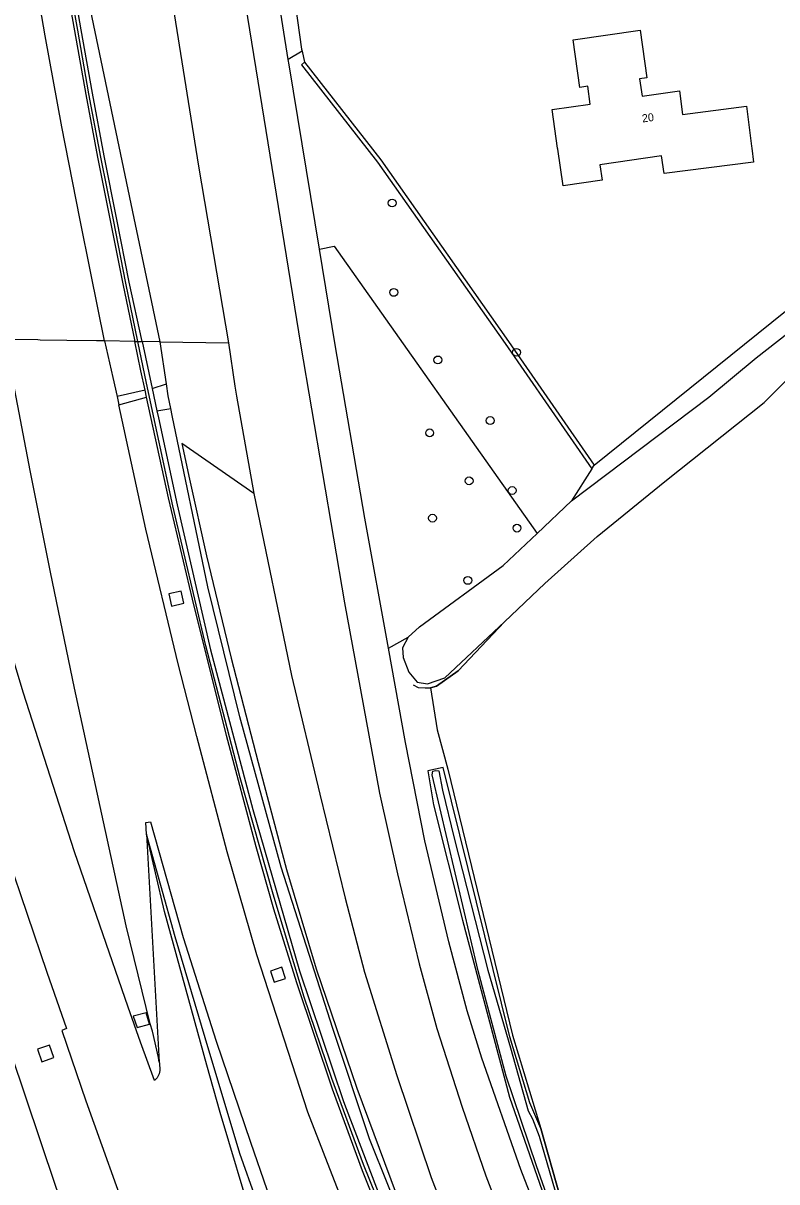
# Model space of a CAD drawing. Extents: x 157663 to 158496, y 379212 to 380934.
# Drawn here: x 158053.2 to 158147.4, y 379870.8 to 380015.6 of the extents above; entities that cross this region are included whole.
import ezdxf

# ---------------------------------------------------------------- set-up
doc = ezdxf.new("R2010")
doc.units = 0
for name, color, linetype in [('IMGEO_Berm_groen', 7, 'Continuous'), ('IMGEO_Boom', 7, 'Continuous'), ('IMGEO_Geluidsscherm', 7, 'Continuous'), ('IMGEO_Grasland_agrarisch', 7, 'Continuous'), ('IMGEO_Grasland_overig', 7, 'Continuous'), ('IMGEO_Groenvoorziening', 7, 'Continuous'), ('IMGEO_Haag', 7, 'Continuous'), ('IMGEO_Loofbos', 7, 'Continuous'), ('IMGEO_Muur', 7, 'Continuous'), ('IMGEO_Pand', 7, 'Continuous'), ('IMGEO_Pand_nummerreeks', 7, 'Continuous'), ('IMGEO_Rijbaan_autosnelweg', 7, 'Continuous'), ('IMGEO_Rijbaan_autoweg', 7, 'Continuous'), ('IMGEO_Rijbaan_lokaal_gesloten', 7, 'Continuous'), ('IMGEO_Voetpad_open', 7, 'Continuous'), ('IMGEO_Waterloop', 7, 'Continuous')]:
    doc.layers.add(name, color=color, linetype=linetype)

msp = doc.modelspace()

# ---------------------------------------------------------------- linework, layer by layer
at = {"layer": 'IMGEO_Berm_groen'}
for points in [[(158070.28, 379975.76), (158067.02, 379991.23), (158061.77, 380016.32), (158058.71, 380034.08), (158055, 380058.15), (158051.86, 380080.14), (158049.08, 380102.23), (158046.65, 380128.62), (158044.45, 380148.29), (158042.26, 380166.46), (158039.47, 380190.15), (158036.64, 380215.73), (158033.77, 380237.86), (158032.18, 380253.23), (158031.7, 380255.1), (158031.04, 380256.7), (158030.21, 380257.79), (158029.14, 380258.85), (158028.41, 380259.51), (158027.77, 380259.76), (158027.29, 380259.77)], [(158067.13, 379975.82), (158063.34, 379975.88)], [(158070.28, 379975.76), (158068.04, 379975.8)], [(158071.09, 379970.51), (158070.28, 379975.76)], [(158070.28, 379975.76), (158078.84, 379975.63)], [(158078.84, 379975.63), (158079.64, 379970.25), (158079.83, 379969), (158082.02, 379956.8)], [(158069.28, 379969.96), (158071.09, 379970.51)], [(158071.63, 379967.44), (158071.3, 379969.01), (158071.09, 379970.51)], [(158069.88, 379967.15), (158071.63, 379967.44)], [(158103.59, 379858.4), (158096.46, 379876.15), (158091.88, 379889.96), (158088.91, 379899.2), (158085.42, 379910.11), (158080.26, 379928.91), (158076.26, 379945.14), (158071.81, 379966.55), (158071.63, 379967.44)], [(158082.02, 379956.8), (158073, 379963.08), (158073.95, 379958.59), (158076.08, 379949.01), (158079.16, 379936.22), (158082.53, 379923.2), (158086.09, 379909.8), (158089.8, 379897.39), (158094.88, 379882.5), (158099.81, 379869.28), (158105.41, 379855.93), (158111.87, 379842.07), (158119.14, 379828.04), (158125.14, 379817.02), (158132.73, 379804.67), (158141.39, 379791.54), (158151.5, 379777.81), (158159.83, 379766.76), (158169.94, 379755.1), (158179.14, 379745.34), (158189.81, 379734.9), (158199.88, 379725.98), (158204.61, 379721.89), (158211.7, 379715.41)], [(158082.02, 379956.8), (158086.71, 379934.07), (158090.25, 379919.25), (158093.43, 379906.24), (158095.86, 379897), (158099.89, 379884.07), (158104.19, 379871.31), (158108.15, 379861.05), (158111.29, 379853.08), (158115.22, 379845.26), (158119.15, 379837.67), (158123.49, 379830.03), (158128.55, 379820.65), (158133.37, 379812.71), (158137.74, 379805.48), (158139.52, 379802.86), (158144.2, 379796), (158146.84, 379792.42)], [(158089.22, 379783.97), (158088.02, 379785.82), (158085.98, 379792.4), (158082.17, 379805.41), (158076.59, 379820.53), (158069.22, 379837.24), (158061.91, 379856.81), (158057.21, 379870.32), (158049.76, 379892.42), (158045.19, 379909.62), (158042.69, 379920.65), (158040.48, 379933.22), (158037.72, 379947.61), (158034.38, 379955.01)], [(158073.25, 379943.1), (158072.9, 379944.62), (158071.36, 379944.27), (158071.71, 379942.75), (158073.25, 379943.1)], [(158084.34, 379862.8), (158080.26, 379874.32), (158075.91, 379888.79), (158072.15, 379901.42), (158068.6, 379914.23)], [(158085.95, 379896.2), (158085.49, 379897.59), (158084.07, 379897.12), (158084.54, 379895.73), (158085.95, 379896.2)], [(158068.95, 379890.48), (158068.56, 379891.9), (158066.93, 379891.47), (158067.42, 379890.05), (158068.95, 379890.48)], [(158056.99, 379886.31), (158056.44, 379887.86), (158054.97, 379887.34), (158055.51, 379885.79), (158056.99, 379886.31)]]:
    msp.add_lwpolyline(points, dxfattribs=at)
at = {"layer": 'IMGEO_Boom'}
for centre in [(158099.3, 379993.12), (158099.51, 379981.95), (158105.02, 379973.51), (158114.85, 379974.46), (158111.56, 379965.93), (158103.99, 379964.39), (158108.93, 379958.39), (158114.31, 379957.19), (158104.35, 379953.73), (158114.91, 379952.49), (158108.77, 379945.95)]:
    msp.add_circle(centre, 0.489, dxfattribs=at)
at = {"layer": 'IMGEO_Geluidsscherm'}
for points in [[(158067.51, 379975.81), (158066.01, 379983.12), (158064.44, 379991.02), (158062.87, 379998.87), (158061.39, 380006.77), (158059.99, 380014.72), (158058.56, 380022.62)], [(158120.8, 379819.79), (158114.51, 379831.41), (158107.79, 379845.08), (158102.16, 379857.08), (158095.73, 379872.94), (158091.74, 379883.71), (158088.29, 379893.87), (158084.41, 379906.73), (158080.3, 379921.26), (158076, 379937.78), (158071.87, 379955.29), (158068.59, 379970.6), (158067.51, 379975.81)]]:
    msp.add_lwpolyline(points, dxfattribs=at)
at = {"layer": 'IMGEO_Grasland_agrarisch'}
for points in [[(158113.37, 379940.77), (158107.57, 379934.65), (158104.86, 379932.73), (158104.08, 379932.54), (158104.94, 379927.29), (158106.26, 379922.36), (158114.34, 379889.1), (158117.88, 379877.44)], [(158156.71, 379803.88), (158152.34, 379809.65), (158148.03, 379816.02), (158135.78, 379836.47), (158132.23, 379842.22), (158127.92, 379850.27), (158123.42, 379860.31), (158120.27, 379869.03), (158117.88, 379877.44)]]:
    msp.add_lwpolyline(points, dxfattribs=at)
at = {"layer": 'IMGEO_Grasland_overig'}
msp.add_lwpolyline([(158072.04, 380016.77), (158075.1, 379997.75), (158078.84, 379975.63)], dxfattribs=at)
at = {"layer": 'IMGEO_Groenvoorziening'}
for points in [[(158077.51, 380124.52), (158073.04, 380120), (158076.45, 380093.04), (158082.12, 380052.43), (158083, 380046.16), (158083.77, 380042.53), (158087.97, 380012.35), (158088.03, 380012.11)], [(158117.88, 379877.44), (158116.53, 379880.63), (158114.03, 379888.9), (158105.68, 379922.57), (158103.76, 379922.17), (158104.46, 379917.9), (158108.08, 379903.48), (158113.98, 379881.36), (158122.11, 379858.07), (158129.01, 379844.29), (158136.4, 379830.77), (158146.01, 379815.34), (158152.98, 379804.81), (158158.6, 379797.46), (158164.69, 379789.7), (158167.62, 379786.4), (158168.19, 379785.83), (158168.61, 379785.66), (158169.02, 379785.67), (158169.42, 379785.89), (158169.79, 379786.34), (158169.81, 379786.59)]]:
    msp.add_lwpolyline(points, dxfattribs=at)
at = {"layer": 'IMGEO_Haag'}
for points in [[(158088.36, 380010.72), (158087.97, 380010.41), (158097.47, 379998.21), (158113.43, 379975.55), (158124.27, 379959.89)], [(158088.36, 380010.72), (158097.87, 379998.51), (158113.84, 379975.83), (158124.56, 379960.34)], [(158124.27, 379959.89), (158124.56, 379960.34)]]:
    msp.add_lwpolyline(points, dxfattribs=at)
at = {"layer": 'IMGEO_Loofbos'}
for points in [[(158124.56, 379960.34), (158206.82, 380026.58), (158196.92, 380075.27), (158189.71, 380112.85)], [(158088.03, 380012.11), (158086.31, 380011.05)], [(158088.03, 380012.11), (158088.36, 380010.72)], [(158090.2, 379987.34), (158092.04, 379987.73), (158117.43, 379951.82)], [(158124.27, 379959.89), (158121.73, 379955.91)], [(158098.83, 379937.48), (158101.29, 379938.85)]]:
    msp.add_lwpolyline(points, dxfattribs=at)
at = {"layer": 'IMGEO_Muur'}
for points in [[(158058.18, 380022.56), (158059.58, 380014.65), (158060.99, 380006.7), (158062.44, 379998.85), (158064.04, 379990.93), (158065.61, 379983.03), (158067.13, 379975.82)], [(158068.04, 379975.8), (158066.43, 379983.21), (158064.88, 379991.06), (158063.28, 379999.03), (158061.81, 380006.86), (158060.4, 380014.76), (158059.02, 380022.74)], [(158068.4, 379969.75), (158067.87, 379972.16), (158067.13, 379975.82)], [(158067.13, 379975.82), (158068.04, 379975.8)], [(158068.04, 379975.8), (158069.28, 379969.96)], [(158068.6, 379968.86), (158068.4, 379969.75)], [(158069.28, 379969.96), (158069.88, 379967.15)], [(158099.71, 379861.87), (158095.59, 379872.16), (158091.85, 379882.36), (158087.38, 379895.65), (158084.52, 379904.87), (158082.31, 379912.63), (158078.59, 379926.55), (158074.33, 379943.6), (158071.35, 379956.29), (158068.6, 379968.86)], [(158113.37, 379940.77), (158118.38, 379945.55), (158124.93, 379951.44), (158133.39, 379958.3), (158145.82, 379968.18)], [(158069.88, 379967.15), (158070.07, 379966.28), (158072.41, 379955.41), (158076.6, 379937.27), (158081.88, 379917.33), (158087.73, 379897.17), (158093.22, 379880.82), (158098.21, 379867.73)], [(158104.08, 379932.54), (158104.86, 379932.73), (158107.57, 379934.65), (158113.37, 379940.77)], [(158101.93, 379932.89), (158102.55, 379932.58), (158103.44, 379932.53), (158104.08, 379932.54)], [(158104.94, 379927.29), (158106.26, 379922.36), (158114.34, 379889.1), (158117.88, 379877.44)], [(158117.88, 379877.44), (158120.27, 379869.03), (158123.42, 379860.31), (158127.92, 379850.27), (158132.23, 379842.22), (158135.78, 379836.47), (158148.03, 379816.02), (158152.34, 379809.65), (158156.71, 379803.88)]]:
    msp.add_lwpolyline(points, dxfattribs=at)
at = {"layer": 'IMGEO_Pand'}
msp.add_lwpolyline([(158143.6, 380005.21), (158144.23, 380000.25), (158144.27, 380000), (158144.49, 379998.24), (158133.32, 379996.8), (158132.99, 379999.03), (158125.27, 379997.88), (158125.55, 379995.99), (158120.71, 379995.27), (158120.02, 379999.86), (158120, 380000), (158119.33, 380004.81), (158124.07, 380005.47), (158123.76, 380007.71), (158122.76, 380007.57), (158121.93, 380013.54), (158130.34, 380014.71), (158131.17, 380008.79), (158130.24, 380008.66), (158130.55, 380006.49), (158135.25, 380007.15), (158135.63, 380004.19), (158143.6, 380005.21)], dxfattribs=at)
at = {"layer": 'IMGEO_Rijbaan_autosnelweg'}
for points in [[(158032.24, 379976.37), (158035.44, 379963.74), (158039.31, 379949.57), (158044.64, 379931.97), (158048.42, 379920.29), (158051.21, 379911.48), (158056.1, 379896.97), (158058.59, 379889.93), (158058, 379889.69), (158060.99, 379880.91), (158066.8, 379864.72), (158074.61, 379842.88), (158080.45, 379825.92), (158084.61, 379813.32), (158088.56, 379800.89), (158091.4, 379791.19), (158091.77, 379789.47), (158092.69, 379785.73)], [(158070.18, 379885.75), (158070.21, 379885.63), (158070.24, 379884.71), (158070.15, 379884.27), (158069.9, 379883.77), (158069.59, 379883.45), (158067.85, 379888.25), (158066.27, 379892.62), (158062.73, 379902.86), (158059.56, 379912.04), (158053.14, 379931.98), (158047.55, 379950.62), (158044.06, 379963.6), (158040.86, 379976.19)], [(158112.85, 379752.23), (158110.21, 379764.83), (158105.88, 379783.9), (158104.32, 379790.7), (158101.74, 379799.81), (158098.93, 379809.39), (158096.44, 379818.03), (158093.64, 379827), (158091.3, 379834.88), (158089.5, 379841.11), (158087.05, 379849.01), (158082.02, 379865.34), (158077.8, 379879.44), (158076.12, 379885.36), (158070.84, 379904.56), (158068.6, 379914.23)], [(158068.6, 379914.23), (158070.18, 379885.75)]]:
    msp.add_lwpolyline(points, dxfattribs=at)
at = {"layer": 'IMGEO_Rijbaan_autoweg'}
for points in [[(158063.34, 379975.88), (158061.6, 379984.36), (158060.23, 379991.17), (158057.99, 380002.65), (158055.92, 380014.02), (158053.88, 380025.89)], [(158070.18, 379885.75), (158070.08, 379886.32), (158069.32, 379889.6), (158069.05, 379890.53), (158066.04, 379902.79), (158062.99, 379916.72), (158059.56, 379932.47), (158056.57, 379946.97), (158054.03, 379959.71), (158050.92, 379976.07)], [(158063.34, 379975.88), (158062.32, 379975.89), (158058.6, 379975.95), (158055.28, 379976), (158055.01, 379976.01), (158051.72, 379976.06), (158050.92, 379976.07)], [(158063.34, 379975.88), (158064.38, 379971.32), (158064.9, 379968.94)], [(158064.9, 379968.94), (158065.12, 379967.91)], [(158211.11, 379707.29), (158203.08, 379713.82), (158195.43, 379720.52), (158188.74, 379726.61), (158181.41, 379733.75), (158172.96, 379742.49), (158167.99, 379748.03), (158158.86, 379757.98), (158150.28, 379768.44), (158139.62, 379782.79), (158132.41, 379792.92), (158125.95, 379802.85), (158117.84, 379816.68), (158110.67, 379829.92), (158106.13, 379838.51), (158101.73, 379847.87), (158094.63, 379864.36), (158088.77, 379879.48), (158082.36, 379899.16), (158078.66, 379912.01), (158074.86, 379926.43), (158072.53, 379935.53), (158068.5, 379952.34), (158065.12, 379967.91)], [(158068.6, 379914.23), (158068.5, 379915.71), (158069.09, 379915.77), (158073.18, 379901.33), (158077.28, 379888.34), (158081.6, 379875.72), (158083.63, 379869.82), (158084.54, 379867.38)]]:
    msp.add_lwpolyline(points, dxfattribs=at)
at = {"layer": 'IMGEO_Rijbaan_lokaal_gesloten'}
for points in [[(158086.31, 380011.05), (158083.64, 380027.93), (158076.88, 380073.51), (158073.72, 380095.84), (158071.15, 380114.74), (158069.06, 380130.96)], [(158080.96, 380017.87), (158087.84, 379975.48), (158093.35, 379943.14), (158097.73, 379919.37), (158099.98, 379909.27), (158102.67, 379898.04), (158104.88, 379889.93), (158108.05, 379880.09), (158111.02, 379871.54), (158114.65, 379862.11)], [(158090.2, 379987.34), (158086.41, 380010.4), (158086.31, 380011.05)], [(158098.83, 379937.48), (158095.88, 379953.73), (158092.16, 379975.41), (158090.2, 379987.34)], [(158118.14, 379865.22), (158115.4, 379872.32), (158110.5, 379886.22), (158108.7, 379892.15), (158106.39, 379900.77), (158103.37, 379913.4), (158100.97, 379925.71), (158098.83, 379937.48)]]:
    msp.add_lwpolyline(points, dxfattribs=at)
at = {"layer": 'IMGEO_Voetpad_open'}
for points in [[(158068.4, 379969.75), (158064.9, 379968.94)], [(158065.12, 379967.91), (158068.6, 379968.86)]]:
    msp.add_lwpolyline(points, dxfattribs=at)
at = {"layer": 'IMGEO_Waterloop'}
for points in [[(158121.73, 379955.91), (158138.92, 379968.84), (158144.83, 379973.77), (158178.39, 380000), (158212.3, 380026.7)], [(158113.37, 379940.77), (158118.38, 379945.55), (158124.93, 379951.44), (158133.39, 379958.3), (158145.82, 379968.18), (158149.3, 379971.66), (158153.93, 379975.02)], [(158117.43, 379951.82), (158121.73, 379955.91)], [(158101.29, 379938.85), (158102.74, 379940.13), (158113.19, 379947.8), (158117.43, 379951.82)], [(158101.29, 379938.85), (158100.58, 379937.52), (158100.66, 379936.33), (158101.38, 379934.48), (158102.42, 379933.24), (158103.72, 379933.02), (158105.91, 379933.79), (158113.37, 379940.77)], [(158121.17, 379861.91), (158117.37, 379872.76), (158113.57, 379884), (158110.04, 379897.14), (158104.31, 379921.65), (158104.37, 379922.12), (158104.73, 379922.2), (158105.15, 379922.17), (158105.6, 379919.72), (158107.05, 379913.75), (158111.25, 379897.23), (158114.1, 379887.54), (158116.3, 379879.63), (158116.86, 379878.64), (158117.69, 379876.48), (158120.92, 379865.3)]]:
    msp.add_lwpolyline(points, dxfattribs=at)

# ---------------------------------------------------------------- texts
at = {"layer": 'IMGEO_Pand_nummerreeks'}
msp.add_text('20', height=1, rotation=7.9321, dxfattribs=at).set_placement((158130.62, 380003.19))

doc.saveas('drawing.dxf')
